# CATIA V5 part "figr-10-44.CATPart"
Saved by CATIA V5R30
Part number: Part1
Bounding box of the stored display mesh (mm): x -20 to 20, y -0.339 to 152.641, z -44.55 to 10.195
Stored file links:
  D:\PROJECTS\CATIA V56R 2020\Resources\Parts File\c10_catia_v5_6r2020_prt\figr-10-44.CATPart
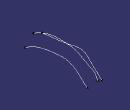
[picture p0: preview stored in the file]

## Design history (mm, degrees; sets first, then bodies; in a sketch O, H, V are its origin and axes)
Set1
  Plane1: type Offset, RefPlane yz-plane, Offset 20, reversed
  Sketch1 on yz-plane, origin (0, 0, 0), H (0, 1, 0), V (0, 0, 1)
    spline S1 through (-0.3393, -8.9363) (20.4957, 1.6782) (43.9804, 9.0119) (85.9797, 8.8277) (110.0875, 1.9736) (113.4186, 0.0053) (148.283, -20.6228) (152.6411, -30.7916)
  Sketch2 on Plane1, origin (-20, 0, 0), H (0, 1, 0), V (0, 0, 1)
    spline S1 through (0, -18.2863) (39.7074, -13.5111) (76.5446, -6.6894) (104.5136, -9.077) (112.3585, -15.8987) (129.7538, -32.6118) (143.3972, -44.5498)
  Plane2: type Offset, RefPlane yz-plane, Offset 20
  Sketch3 on Plane2, origin (20, 0, 0), H (0, 1, 0), V (0, 0, 1)
    spline S1 through (0, -29.0463) (25.3574, -14.3797) (67.652, -5.1704) (115.4039, -10.2866) (140.3031, -31.4339) (148.4891, -38.2556)
Body1 (main body)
